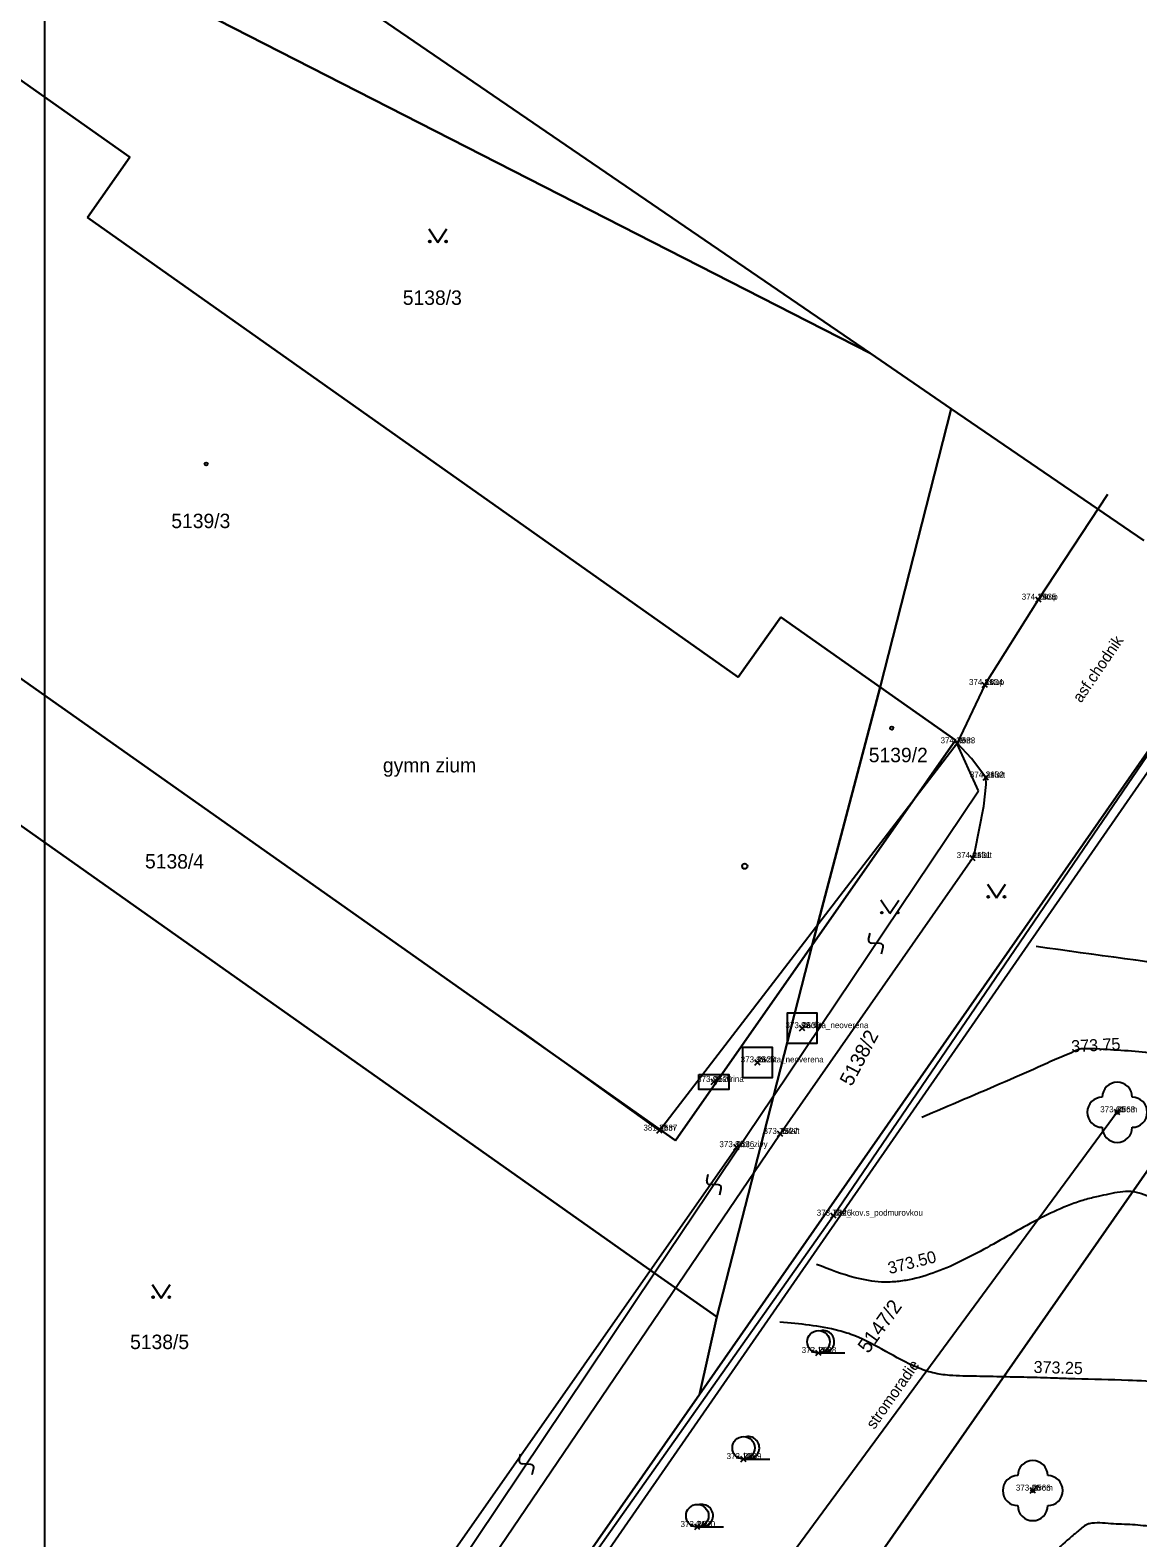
# Model space of a CAD drawing. Extents: x -400488 to -400124, y -1251493 to -1251223.
# Drawn here: x -400397.9 to -400361.1, y -1251319.8 to -1251269.6 of the extents above; entities that cross this region are included whole.
import ezdxf

# ---------------------------------------------------------------- set-up
doc = ezdxf.new("R2010")
doc.units = 0
for name, color, linetype in [('Level 20', 7, 'Continuous'), ('Level 21', 7, 'Continuous'), ('Level 22', 7, 'Continuous'), ('Level 23', 7, 'Continuous'), ('Level 3', 7, 'Continuous'), ('Level 32', 7, 'Continuous'), ('Level 34', 7, 'Continuous'), ('Level 35', 7, 'Continuous'), ('Level 36', 7, 'Continuous'), ('Level 49', 7, 'Continuous'), ('Level 53', 7, 'Continuous'), ('Level 60', 7, 'Continuous'), ('Level 63', 7, 'Continuous')]:
    doc.layers.add(name, color=color, linetype=linetype)

msp = doc.modelspace()

# ---------------------------------------------------------------- linework, layer by layer
at = {"layer": 'Level 20'}
for p, q in [((-400364.458, -1251288.688), (-400364.282, -1251288.512)), ((-400364.282, -1251288.688), (-400364.458, -1251288.512)), ((-400366.238, -1251291.528), (-400366.062, -1251291.352)), ((-400366.062, -1251291.528), (-400366.238, -1251291.352)), ((-400367.158, -1251293.468), (-400366.982, -1251293.292)), ((-400366.982, -1251293.468), (-400367.158, -1251293.292)), ((-400366.208, -1251294.608), (-400366.032, -1251294.432)), ((-400366.032, -1251294.608), (-400366.208, -1251294.432)), ((-400366.648, -1251297.288), (-400366.472, -1251297.112)), ((-400366.472, -1251297.288), (-400366.648, -1251297.112)), ((-400372.318, -1251302.948), (-400372.142, -1251302.772)), ((-400372.142, -1251302.948), (-400372.318, -1251302.772)), ((-400373.808, -1251304.088), (-400373.632, -1251303.912)), ((-400373.632, -1251304.088), (-400373.808, -1251303.912)), ((-400375.258, -1251304.738), (-400375.082, -1251304.562)), ((-400375.082, -1251304.738), (-400375.258, -1251304.562)), ((-400361.838, -1251305.748), (-400361.662, -1251305.572)), ((-400361.662, -1251305.748), (-400361.838, -1251305.572)), ((-400377.068, -1251306.358), (-400376.892, -1251306.182)), ((-400376.892, -1251306.358), (-400377.068, -1251306.182)), ((-400374.508, -1251306.908), (-400374.332, -1251306.732)), ((-400374.332, -1251306.908), (-400374.508, -1251306.732)), ((-400373.048, -1251306.468), (-400372.872, -1251306.292)), ((-400372.872, -1251306.468), (-400373.048, -1251306.292)), ((-400371.278, -1251309.188), (-400371.102, -1251309.012)), ((-400371.102, -1251309.188), (-400371.278, -1251309.012)), ((-400371.778, -1251313.758), (-400371.602, -1251313.582)), ((-400371.602, -1251313.758), (-400371.778, -1251313.582)), ((-400374.268, -1251317.288), (-400374.092, -1251317.112)), ((-400374.092, -1251317.288), (-400374.268, -1251317.112)), ((-400364.648, -1251318.338), (-400364.472, -1251318.162)), ((-400364.472, -1251318.338), (-400364.648, -1251318.162)), ((-400375.808, -1251319.548), (-400375.632, -1251319.372)), ((-400375.632, -1251319.548), (-400375.808, -1251319.372))]:
    msp.add_line(p, q, dxfattribs=at)
at = {"layer": 'Level 3'}
msp.add_lwpolyline([(-400397.431, -1251233.087), (-400250.431, -1251233.087), (-400250.431, -1251440.987), (-400397.431, -1251440.987)], close=True, dxfattribs=at)
at = {"layer": 'Level 32'}
msp.add_lwpolyline([(-400392.73, -1251328.88), (-400391.51, -1251329.08), (-400390.794, -1251329.059), (-400390.02, -1251328.98), (-400389.409, -1251328.705), (-400389, -1251328.44), (-400388.19, -1251327.81), (-400382.7, -1251320.73), (-400372.96, -1251306.38), (-400366.56, -1251297.2), (-400366.487, -1251296.989), (-400366.185, -1251295.472), (-400366.11, -1251294.75), (-400366.12, -1251294.52), (-400366.6, -1251293.882), (-400367.07, -1251293.38)], dxfattribs=at)
at = {"layer": 'Level 34'}
for points in [[(-400367.13, -1251293.28), (-400372.94, -1251289.18)], [(-400376.98, -1251306.27), (-400367.07, -1251293.38)], [(-400376.98, -1251306.27), (-400381.602, -1251302.933)]]:
    msp.add_lwpolyline(points, dxfattribs=at)
msp.add_circle((-400374.141, -1251297.472), 0.0875, dxfattribs=at)
at = {"layer": 'Level 35'}
for points in [[(-400364.37, -1251288.6), (-400362.061, -1251285.089)], [(-400366.15, -1251291.44), (-400364.37, -1251288.6)], [(-400380.18, -1251321.83), (-400371.19, -1251309.1), (-400359.12, -1251291.4)], [(-400366.15, -1251291.44), (-400367.07, -1251293.38)], [(-400343.3, -1251302.69), (-400343.6, -1251302.78), (-400345.93, -1251301.42), (-400359.09, -1251291.97), (-400380.09, -1251322.28), (-400384.96, -1251329.11), (-400372.26, -1251338.33), (-400358.88, -1251348.03)], [(-400392.66, -1251328.664), (-400391.502, -1251328.775), (-400391.078, -1251328.805), (-400390.539, -1251328.775), (-400390.012, -1251328.676), (-400389.62, -1251328.55), (-400374.42, -1251306.82)]]:
    msp.add_lwpolyline(points, dxfattribs=at)
at = {"layer": 'Level 36'}
for p, q in [((-400369.316, -1251299.046), (-400369.616, -1251298.596)), ((-400369.316, -1251299.046), (-400369.016, -1251298.596)), ((-400371.69, -1251313.67), (-400370.815, -1251313.67)), ((-400374.18, -1251317.2), (-400373.305, -1251317.2)), ((-400375.72, -1251319.46), (-400374.845, -1251319.46))]:
    msp.add_line(p, q, dxfattribs=at)
msp.add_lwpolyline([(-400361.75, -1251305.66), (-400376.03, -1251325.06)], dxfattribs=at)
for centre, radius in [((-400369.586, -1251299.016), 0.03), ((-400369.046, -1251299.016), 0.03), ((-400361.75, -1251305.66), 0.05), ((-400371.69, -1251313.295), 0.375), ((-400374.18, -1251316.825), 0.375), ((-400364.56, -1251318.25), 0.05), ((-400375.72, -1251319.085), 0.375)]:
    msp.add_circle(centre, radius, dxfattribs=at)
for centre, radius, start, end in [((-400361.75, -1251305.16), 0.5, 0, 180), ((-400362.25, -1251305.66), 0.5, 90, 270), ((-400361.25, -1251305.66), 0.5, 270, 90), ((-400361.75, -1251306.16), 0.5, 180, 0), ((-400371.54, -1251313.295), 0.375, 270, 101.537), ((-400374.03, -1251316.825), 0.375, 270, 101.537), ((-400364.56, -1251317.75), 0.5, 0, 180), ((-400365.06, -1251318.25), 0.5, 90, 270), ((-400364.06, -1251318.25), 0.5, 270, 90), ((-400375.57, -1251319.085), 0.375, 270, 101.537), ((-400364.56, -1251318.75), 0.5, 180, 0)]:
    msp.add_arc(centre, radius, start, end, dxfattribs=at)
at = {"layer": 'Level 49'}
for points in [[(-400342.338, -1251309.931), (-400342.926, -1251309.741), (-400343.403, -1251309.632), (-400343.7, -1251309.621), (-400343.998, -1251309.649), (-400345.067, -1251309.285), (-400345.407, -1251308.822), (-400345.721, -1251308.352), (-400346.087, -1251307.924), (-400346.398, -1251307.637), (-400347.239, -1251306.906), (-400348.093, -1251306.191), (-400349.765, -1251304.717), (-400349.777, -1251304.701), (-400351.677, -1251303.581), (-400351.722, -1251303.572), (-400351.728, -1251303.567), (-400352.566, -1251303.179), (-400353.445, -1251302.853), (-400354.315, -1251302.505), (-400355.121, -1251302.048), (-400355.747, -1251301.563), (-400356.101, -1251301.255), (-400356.253, -1251301.223), (-400356.406, -1251301.202), (-400356.712, -1251301.168), (-400357.324, -1251301.088), (-400358.547, -1251300.933), (-400364.448, -1251300.144)], [(-400343.209, -1251311.253), (-400343.532, -1251311.179), (-400344.172, -1251311.146), (-400344.816, -1251311.218), (-400345.461, -1251311.313), (-400346.105, -1251311.346), (-400346.116, -1251311.344), (-400346.287, -1251311.229), (-400346.431, -1251311.087), (-400346.569, -1251310.941), (-400346.723, -1251310.818), (-400346.9, -1251310.714), (-400347.083, -1251310.62), (-400347.265, -1251310.526), (-400347.439, -1251310.419), (-400348.288, -1251309.813), (-400349.125, -1251309.188), (-400349.962, -1251308.561), (-400350.811, -1251307.952), (-400352.125, -1251307.062), (-400352.799, -1251306.642), (-400353.489, -1251306.24), (-400355.033, -1251305.509), (-400356.643, -1251304.939), (-400357.283, -1251304.758), (-400357.939, -1251304.623), (-400358.583, -1251304.46), (-400359.188, -1251304.2), (-400359.21, -1251304.186), (-400359.228, -1251304.175), (-400361.036, -1251303.648), (-400361.979, -1251303.582), (-400362.918, -1251303.549), (-400362.946, -1251303.551), (-400363.275, -1251303.682), (-400363.596, -1251303.817), (-400364.226, -1251304.092), (-400365.474, -1251304.643), (-400368.248, -1251305.829)], [(-400348.13, -1251314.015), (-400348.581, -1251313.91), (-400349.024, -1251313.784), (-400349.884, -1251313.458), (-400351.284, -1251312.811), (-400352.678, -1251312.155), (-400354.07, -1251311.497), (-400355.466, -1251310.843), (-400358.195, -1251309.587), (-400359.564, -1251308.973), (-400360.94, -1251308.376), (-400361.287, -1251308.297), (-400361.654, -1251308.313), (-400362.024, -1251308.382), (-400362.38, -1251308.461), (-400362.61, -1251308.513), (-400362.839, -1251308.576), (-400363.294, -1251308.73), (-400364.197, -1251309.13), (-400365.983, -1251310.108), (-400367.769, -1251310.974), (-400368.672, -1251311.234), (-400369.128, -1251311.297), (-400369.357, -1251311.31), (-400369.587, -1251311.308), (-400370.466, -1251311.167), (-400371.752, -1251310.724)], [(-400347.932, -1251317.716), (-400349.041, -1251317.416), (-400350.16, -1251317.169), (-400351.4, -1251316.95), (-400352.643, -1251316.75), (-400353.885, -1251316.547), (-400355.123, -1251316.318), (-400355.703, -1251316.162), (-400356.138, -1251315.979), (-400356.561, -1251315.774), (-400356.981, -1251315.562), (-400357.408, -1251315.363), (-400358.207, -1251314.997), (-400358.615, -1251314.845), (-400358.825, -1251314.789), (-400359.039, -1251314.751), (-400360.213, -1251314.639), (-400361.389, -1251314.581), (-400363.153, -1251314.532), (-400363.741, -1251314.512), (-400364.638, -1251314.485), (-400365.536, -1251314.466), (-400366.433, -1251314.446), (-400367.33, -1251314.416), (-400367.882, -1251314.331), (-400368.415, -1251314.147), (-400369.451, -1251313.617), (-400370.485, -1251313.098), (-400371.017, -1251312.928), (-400372.971, -1251312.64)], [(-400352.293, -1251323.278), (-400352.826, -1251323.097), (-400352.844, -1251323.089), (-400354.58, -1251322.223), (-400356.287, -1251321.302), (-400358.007, -1251320.393), (-400358.886, -1251319.963), (-400359.784, -1251319.561), (-400359.802, -1251319.557), (-400360.521, -1251319.456), (-400361.243, -1251319.387), (-400361.966, -1251319.353), (-400362.686, -1251319.354), (-400362.706, -1251319.359), (-400363.04, -1251319.588), (-400363.343, -1251319.84), (-400363.891, -1251320.382), (-400364.419, -1251320.929), (-400364.995, -1251321.421), (-400366.014, -1251322.099), (-400366.527, -1251322.437), (-400367.024, -1251322.796), (-400367.495, -1251323.197), (-400367.955, -1251323.654), (-400368.388, -1251324.135), (-400368.82, -1251324.624), (-400370.184, -1251324.602), (-400371.084, -1251324.11), (-400371.985, -1251323.601), (-400372.84, -1251323.028), (-400374.376, -1251321.785), (-400375.093, -1251321.106), (-400376.539, -1251320.249), (-400376.957, -1251320.548), (-400377.775, -1251321.215), (-400378.615, -1251321.804), (-400379.061, -1251322.005), (-400379.52, -1251322.108)]]:
    msp.add_spline(points, degree=3, dxfattribs=at)
at = {"layer": 'Level 53'}
msp.add_lwpolyline([(-400375.67, -1251304.4), (-400374.67, -1251304.4), (-400374.67, -1251304.9), (-400375.67, -1251304.9)], close=True, dxfattribs=at)
at = {"layer": 'Level 60'}
for points in [[(-400372.73, -1251303.36), (-400371.73, -1251303.36), (-400371.73, -1251302.36), (-400372.73, -1251302.36)], [(-400374.22, -1251304.5), (-400373.22, -1251304.5), (-400373.22, -1251303.5), (-400374.22, -1251303.5)]]:
    msp.add_lwpolyline(points, close=True, dxfattribs=at)
at = {"layer": 'Level 63'}
for p, q in [((-400395.04, -1251263.25), (-400369.97, -1251280.4)), ((-400369.97, -1251280.4), (-400395.04, -1251263.25)), ((-400401.86, -1251264.1), (-400369.97, -1251280.4)), ((-400369.97, -1251280.4), (-400401.86, -1251264.1)), ((-400394.6, -1251273.88), (-400400.44, -1251269.76)), ((-400400.44, -1251269.76), (-400394.6, -1251273.88)), ((-400396.01, -1251275.88), (-400394.6, -1251273.88)), ((-400394.6, -1251273.88), (-400396.01, -1251275.88)), ((-400374.36, -1251291.18), (-400396.01, -1251275.88)), ((-400396.01, -1251275.88), (-400374.36, -1251291.18)), ((-400384.65, -1251276.26), (-400384.35, -1251276.71)), ((-400384.35, -1251276.71), (-400384.05, -1251276.26)), ((-400369.97, -1251280.4), (-400367.27, -1251282.25)), ((-400367.27, -1251282.25), (-400369.97, -1251280.4)), ((-400367.27, -1251282.25), (-400369.64, -1251291.51)), ((-400369.64, -1251291.51), (-400367.27, -1251282.25)), ((-400367.27, -1251282.25), (-400360.87, -1251286.63)), ((-400360.87, -1251286.63), (-400367.27, -1251282.25)), ((-400407.46, -1251284.71), (-400376.45, -1251306.6)), ((-400376.45, -1251306.6), (-400407.46, -1251284.71)), ((-400408.63, -1251288.78), (-400377.14, -1251311.01)), ((-400377.14, -1251311.01), (-400408.63, -1251288.78)), ((-400372.94, -1251289.18), (-400374.36, -1251291.18)), ((-400374.36, -1251291.18), (-400372.94, -1251289.18)), ((-400369.64, -1251291.51), (-400372.94, -1251289.18)), ((-400372.94, -1251289.18), (-400369.64, -1251291.51)), ((-400375.65, -1251315.05), (-400359.15, -1251291.37)), ((-400359.15, -1251291.37), (-400375.65, -1251315.05)), ((-400369.64, -1251291.51), (-400371.9, -1251300.1)), ((-400371.9, -1251300.1), (-400369.64, -1251291.51)), ((-400367.13, -1251293.28), (-400369.64, -1251291.51)), ((-400369.64, -1251291.51), (-400367.13, -1251293.28)), ((-400371.9, -1251300.1), (-400367.13, -1251293.28)), ((-400367.13, -1251293.28), (-400371.9, -1251300.1)), ((-400366.37, -1251294.96), (-400367.13, -1251293.28)), ((-400373.19, -1251305.12), (-400366.37, -1251294.96)), ((-400352.67, -1251296), (-400379.03, -1251333.83)), ((-400379.03, -1251333.83), (-400352.67, -1251296)), ((-400366.07, -1251298.07), (-400365.77, -1251298.52)), ((-400365.77, -1251298.52), (-400365.47, -1251298.07)), ((-400370.021, -1251299.913), (-400369.973, -1251299.695)), ((-400376.45, -1251306.6), (-400371.9, -1251300.1)), ((-400371.9, -1251300.1), (-400376.45, -1251306.6)), ((-400371.9, -1251300.1), (-400373.19, -1251305.12)), ((-400373.19, -1251305.12), (-400371.9, -1251300.1)), ((-400369.633, -1251300.046), (-400369.927, -1251300.034)), ((-400369.587, -1251300.385), (-400369.539, -1251300.167)), ((-400373.19, -1251305.12), (-400377.14, -1251311.01)), ((-400373.19, -1251305.12), (-400375.07, -1251312.47)), ((-400375.07, -1251312.47), (-400373.19, -1251305.12)), ((-400375.406, -1251307.938), (-400375.358, -1251307.72)), ((-400375.018, -1251308.071), (-400375.312, -1251308.059)), ((-400374.972, -1251308.41), (-400374.924, -1251308.192)), ((-400377.14, -1251311.01), (-400385.67, -1251323.73)), ((-400377.14, -1251311.01), (-400375.07, -1251312.47)), ((-400375.07, -1251312.47), (-400377.14, -1251311.01)), ((-400393.856, -1251311.394), (-400393.556, -1251311.844)), ((-400393.556, -1251311.844), (-400393.256, -1251311.394)), ((-400375.07, -1251312.47), (-400375.65, -1251315.05)), ((-400375.65, -1251315.05), (-400375.07, -1251312.47)), ((-400385.49, -1251329.17), (-400375.65, -1251315.05)), ((-400375.65, -1251315.05), (-400385.49, -1251329.17)), ((-400381.646, -1251317.243), (-400381.598, -1251317.025)), ((-400381.258, -1251317.376), (-400381.552, -1251317.364)), ((-400381.212, -1251317.715), (-400381.164, -1251317.497))]:
    msp.add_line(p, q, dxfattribs=at)
for centre, radius in [((-400384.62, -1251276.68), 0.03), ((-400384.08, -1251276.68), 0.03), ((-400392.06, -1251284.086), 0.054), ((-400369.25, -1251292.876), 0.054), ((-400366.04, -1251298.49), 0.03), ((-400365.5, -1251298.49), 0.03), ((-400393.826, -1251311.814), 0.03), ((-400393.286, -1251311.814), 0.03)]:
    msp.add_circle(centre, radius, dxfattribs=at)
for centre, start, end in [((-400369.923, -1251299.934), 167.7527, 267.7631), ((-400369.637, -1251300.146), 347.753, 87.7631), ((-400375.308, -1251307.959), 167.7527, 267.7631), ((-400375.022, -1251308.171), 347.753, 87.7631), ((-400381.548, -1251317.264), 167.7527, 267.7631), ((-400381.262, -1251317.476), 347.753, 87.7631)]:
    msp.add_arc(centre, 0.1, start, end, dxfattribs=at)

# ---------------------------------------------------------------- texts
at = {"layer": 'Level 21'}
for s, p in [('2635', (-400364.37, -1251288.6)), ('2634', (-400366.15, -1251291.44)), ('2633', (-400367.07, -1251293.38)), ('2632', (-400366.12, -1251294.52)), ('2631', (-400366.56, -1251297.2)), ('2630', (-400372.23, -1251302.86)), ('2628', (-400373.72, -1251304)), ('2629', (-400375.17, -1251304.65)), ('2563', (-400361.75, -1251305.66)), ('2637', (-400376.98, -1251306.27)), ('2627', (-400372.96, -1251306.38)), ('2636', (-400374.42, -1251306.82)), ('2626', (-400371.19, -1251309.1)), ('2568', (-400371.69, -1251313.67)), ('2569', (-400374.18, -1251317.2)), ('2566', (-400364.56, -1251318.25)), ('2570', (-400375.72, -1251319.46))]:
    msp.add_text(s, height=0.2, dxfattribs=at).set_placement(p)
at = {"layer": 'Level 22'}
for s, p in [('vstup', (-400364.37, -1251288.6)), ('vstup', (-400366.15, -1251291.44)), ('dom', (-400367.07, -1251293.38)), ('asfalt', (-400366.12, -1251294.52)), ('asfalt', (-400366.56, -1251297.2)), ('sachta_neoverena', (-400372.23, -1251302.86)), ('sachta_neoverena', (-400373.72, -1251304)), ('el.skrina', (-400375.17, -1251304.65)), ('strom', (-400361.75, -1251305.66)), ('dom', (-400376.98, -1251306.27)), ('asfalt', (-400372.96, -1251306.38)), ('plot_zivy', (-400374.42, -1251306.82)), ('plot_kov.s_podmurovkou', (-400371.19, -1251309.1)), ('krik', (-400371.69, -1251313.67)), ('krik', (-400374.18, -1251317.2)), ('strom', (-400364.56, -1251318.25)), ('krik', (-400375.72, -1251319.46))]:
    msp.add_text(s, height=0.2, dxfattribs=at).set_placement(p)
at = {"layer": 'Level 23'}
for s, p in [('374.29', (-400364.928, -1251288.6)), ('374.31', (-400366.683, -1251291.44)), ('374.29', (-400367.628, -1251293.38)), ('374.21', (-400366.653, -1251294.52)), ('374.21', (-400367.093, -1251297.2)), ('373.98', (-400372.788, -1251302.86)), ('373.99', (-400374.278, -1251304)), ('373.99', (-400375.728, -1251304.65)), ('373.60', (-400362.316, -1251305.66)), ('381.31', (-400377.513, -1251306.27)), ('373.75', (-400373.519, -1251306.38)), ('373.80', (-400374.986, -1251306.82)), ('373.72', (-400371.748, -1251309.1)), ('373.15', (-400372.249, -1251313.67)), ('373.10', (-400374.746, -1251317.2)), ('373.06', (-400365.123, -1251318.25)), ('373.04', (-400376.278, -1251319.46))]:
    msp.add_text(s, height=0.2, dxfattribs=at).set_placement(p)
at = {"layer": 'Level 32'}
msp.add_text('asf.chodnik', height=0.375, rotation=55.8347, dxfattribs=at).set_placement((-400362.954, -1251292.058))
at = {"layer": 'Level 36'}
msp.add_text('stromoradie', height=0.375, rotation=54.938, dxfattribs=at).set_placement((-400369.829, -1251316.234))
at = {"layer": 'Level 49'}
for s, rotation, p in [('373.75', 2.9756, (-400363.269, -1251303.664)), ('373.50', 14.3081, (-400369.323, -1251311.048)), ('373.25', 358.4133, (-400364.536, -1251314.332))]:
    msp.add_text(s, height=0.4, rotation=rotation, dxfattribs=at).set_placement(p)
at = {"layer": 'Level 63'}
for s, p in [('5138/3', (-400385.518, -1251278.79)), ('5139/3', (-400393.22, -1251286.22)), ('5139/2', (-400370.016, -1251294.01)), ('gymn\xa0zium', (-400386.18, -1251294.35)), ('5138/5', (-400394.591, -1251313.54))]:
    msp.add_text(s, height=0.48, dxfattribs=at).set_placement(p)
for s, rotation, p in [('5138/4', 359.63, (-400394.096, -1251297.543)), ('5138/2', 62.26, (-400370.587, -1251304.824)), ('5147/2', 54.332, (-400370.033, -1251313.713))]:
    msp.add_text(s, height=0.48, rotation=rotation, dxfattribs=at).set_placement(p)

doc.saveas('drawing.dxf')
